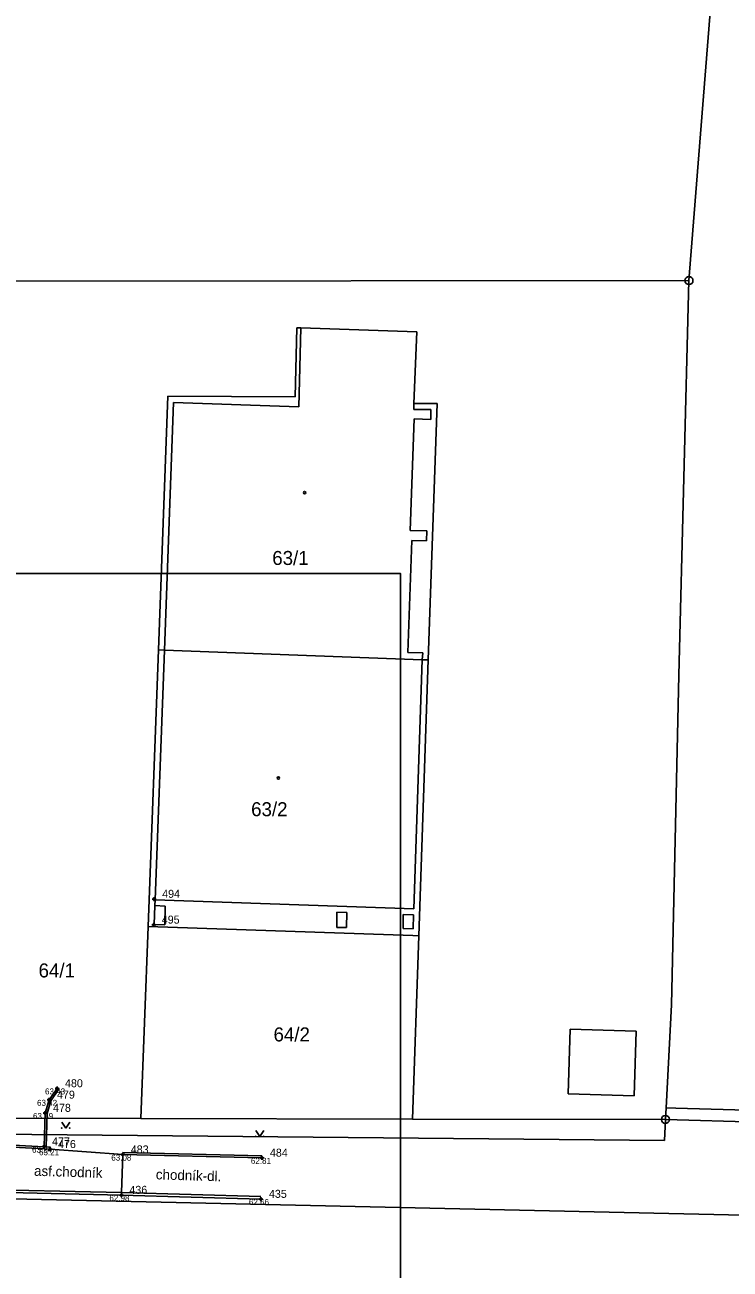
# Model space of a CAD drawing. Extents: x -454285 to -453563, y -1108687 to -1108249.
# Drawn here: x -453808.9 to -453773.6, y -1108476.5 to -1108414.3 of the extents above; entities that cross this region are included whole.
import ezdxf

# ---------------------------------------------------------------- set-up
doc = ezdxf.new("R2010")
doc.units = 0
for name, color, linetype in [('1', 7, 'Continuous'), ('14', 7, 'Continuous'), ('15', 7, 'Continuous'), ('2', 7, 'Continuous'), ('25', 7, 'Continuous'), ('28', 7, 'Continuous'), ('BODY_T1_2018', 7, 'Continuous'), ('CISLA_T1_2018', 7, 'Continuous'), ('obrubník', 7, 'Continuous'), ('rozhraní', 7, 'Continuous'), ('rámy', 7, 'Continuous'), ('T', 7, 'Continuous'), ('VYSKY_T1_2018', 7, 'Continuous'), ('zeleň', 7, 'Continuous')]:
    doc.layers.add(name, color=color, linetype=linetype)

# ---------------------------------------------------------------- blocks, each defined once
blk = doc.blocks.new('Z402')
for start, end in [(0, 180), (180, 0)]:
    blk.add_arc((0, 0), 0.15, start, end)
blk = doc.blocks.new('Z105')
for radius in [0.5, 0.01]:
    blk.add_circle((0, 0), radius)
blk = doc.blocks.new('PARK')
for p, q in [((0, 0), (-1, 1.5)), ((1, 1.5), (0, 0))]:
    blk.add_line(p, q)
for centre, start, end in [((-1, 0), 0, 180), ((1, 0), 0, 180), ((1, 0), 180, 0), ((-1, 0), 180, 0)]:
    blk.add_arc(centre, 0.05, start, end)
blk = doc.blocks.new('POINT_DISPLAY')
for p, q in [((-0.1, 0), (0.1, 0)), ((0, -0.1), (0, 0.1))]:
    blk.add_line(p, q)
blk.add_circle((0, 0), 0.05)
blk = doc.blocks.new('t1_2018')
at = {"layer": 'BODY_T1_2018'}
for p in [(-453802.46, -1108457.98), (-453802.48, -1108459.27), (-453807.32, -1108467.45), (-453807.72, -1108468.02), (-453807.92, -1108468.68), (-453807.97, -1108470.36), (-453807.67, -1108470.49), (-453804.03, -1108470.76), (-453797.07, -1108470.92), (-453804.1, -1108472.78), (-453797.12, -1108472.98)]:
    blk.add_blockref('POINT_DISPLAY', p, dxfattribs=at)
at = {"layer": 'CISLA_T1_2018'}
for s, p in [('494', (-453802.06, -1108457.92)), ('495', (-453802.08, -1108459.21)), ('480', (-453806.92, -1108467.39)), ('479', (-453807.32, -1108467.96)), ('478', (-453807.52, -1108468.62)), ('477', (-453807.57, -1108470.3)), ('476', (-453807.27, -1108470.43)), ('483', (-453803.63, -1108470.7)), ('484', (-453796.67, -1108470.86)), ('436', (-453803.7, -1108472.72)), ('435', (-453796.72, -1108472.92))]:
    blk.add_text(s, height=0.4, dxfattribs=at).set_placement(p)
at = {"layer": 'VYSKY_T1_2018'}
for s, p in [('63.43', (-453807.92, -1108467.75)), ('63.42', (-453808.32, -1108468.32)), ('63.39', (-453808.52, -1108468.98)), ('63.24', (-453808.57, -1108470.66)), ('63.21', (-453808.22, -1108470.79)), ('63.08', (-453804.605, -1108471.06)), ('62.81', (-453797.62, -1108471.22)), ('62.98', (-453804.7, -1108473.08)), ('62.66', (-453797.72, -1108473.28))]:
    blk.add_text(s, height=0.3, dxfattribs=at).set_placement(p)

msp = doc.modelspace()

# ---------------------------------------------------------------- linework, layer by layer
at = {"layer": '1'}
for p, q in [((-453774.627, -1108413.451), (-453775.707, -1108427.061)), ((-453809.507, -1108427.091), (-453775.707, -1108427.061)), ((-453775.707, -1108427.061), (-453776.207, -1108446.791)), ((-453795.317, -1108429.421), (-453795.407, -1108432.871)), ((-453795.317, -1108429.421), (-453795.117, -1108429.431)), ((-453795.117, -1108429.431), (-453789.317, -1108429.621)), ((-453789.317, -1108429.621), (-453789.467, -1108433.201)), ((-453801.777, -1108432.841), (-453802.247, -1108445.521)), ((-453795.407, -1108432.871), (-453801.777, -1108432.841)), ((-453789.467, -1108433.201), (-453788.307, -1108433.211)), ((-453788.307, -1108433.211), (-453788.747, -1108446.031)), ((-453802.247, -1108445.521), (-453802.767, -1108459.361)), ((-453802.247, -1108445.521), (-453801.947, -1108445.541)), ((-453801.947, -1108445.541), (-453789.047, -1108446.021)), ((-453789.217, -1108459.821), (-453788.747, -1108446.031)), ((-453788.747, -1108446.031), (-453789.047, -1108446.021)), ((-453776.207, -1108446.791), (-453776.577, -1108463.271)), ((-453802.767, -1108459.361), (-453803.127, -1108468.961)), ((-453802.767, -1108459.361), (-453789.517, -1108459.811)), ((-453789.217, -1108459.821), (-453789.537, -1108468.981)), ((-453789.517, -1108459.811), (-453789.217, -1108459.821)), ((-453776.577, -1108463.271), (-453776.857, -1108468.421)), ((-453897.257, -1108468.871), (-453776.927, -1108470.061)), ((-453776.857, -1108468.421), (-453776.887, -1108469.001)), ((-453803.127, -1108468.961), (-453811.757, -1108468.941)), ((-453803.127, -1108468.961), (-453789.537, -1108468.981)), ((-453789.537, -1108468.981), (-453776.887, -1108469.001)), ((-453776.887, -1108469.001), (-453776.927, -1108470.061)), ((-453767.457, -1108469.291), (-453776.887, -1108469.001))]:
    msp.add_line(p, q, dxfattribs=at)
at = {"layer": '2'}
for p, q in [((-453795.217, -1108433.371), (-453795.117, -1108429.431)), ((-453801.487, -1108433.151), (-453801.947, -1108445.541)), ((-453801.487, -1108433.151), (-453795.217, -1108433.371)), ((-453789.477, -1108433.501), (-453789.467, -1108433.201)), ((-453789.647, -1108439.551), (-453789.457, -1108433.981)), ((-453788.617, -1108433.511), (-453789.477, -1108433.501)), ((-453789.457, -1108433.981), (-453788.627, -1108434.011)), ((-453788.627, -1108434.011), (-453788.617, -1108433.511)), ((-453788.827, -1108439.581), (-453789.647, -1108439.551)), ((-453788.837, -1108440.081), (-453788.827, -1108439.581)), ((-453789.777, -1108445.651), (-453789.577, -1108440.051)), ((-453789.577, -1108440.051), (-453788.837, -1108440.081)), ((-453801.947, -1108445.541), (-453802.417, -1108458.021)), ((-453789.027, -1108445.671), (-453789.777, -1108445.651)), ((-453789.047, -1108446.021), (-453789.027, -1108445.671)), ((-453789.477, -1108458.471), (-453789.047, -1108446.021)), ((-453802.417, -1108458.021), (-453802.427, -1108458.311)), ((-453789.477, -1108458.471), (-453802.417, -1108458.021)), ((-453802.457, -1108459.261), (-453802.427, -1108458.311)), ((-453802.427, -1108458.311), (-453801.917, -1108458.331)), ((-453801.917, -1108458.331), (-453801.927, -1108459.271)), ((-453793.327, -1108459.411), (-453793.317, -1108458.631)), ((-453793.317, -1108458.631), (-453792.827, -1108458.651)), ((-453792.827, -1108458.651), (-453792.837, -1108459.411)), ((-453790.007, -1108459.461), (-453789.997, -1108458.751)), ((-453789.997, -1108458.751), (-453789.487, -1108458.771)), ((-453789.487, -1108458.771), (-453789.507, -1108459.471)), ((-453801.927, -1108459.271), (-453802.457, -1108459.261)), ((-453792.837, -1108459.411), (-453793.327, -1108459.411)), ((-453789.507, -1108459.471), (-453790.007, -1108459.461)), ((-453781.747, -1108467.721), (-453781.647, -1108464.481)), ((-453781.647, -1108464.481), (-453778.347, -1108464.581)), ((-453778.347, -1108464.581), (-453778.447, -1108467.821)), ((-453778.447, -1108467.821), (-453781.747, -1108467.721)), ((-453776.857, -1108468.421), (-453776.367, -1108468.431)), ((-453767.457, -1108468.701), (-453776.367, -1108468.431)), ((-453670.227, -1108476.061), (-453858.457, -1108471.891))]:
    msp.add_line(p, q, dxfattribs=at)
at = {"layer": 'obrubník'}
for points in [[(-453807.238, -1108467.507), (-453807.629, -1108468.064), (-453807.82, -1108468.696), (-453807.87, -1108470.363), (-453807.97, -1108470.36), (-453807.92, -1108468.68), (-453807.72, -1108468.02), (-453807.32, -1108467.45)], [(-453797.068, -1108470.82), (-453804.028, -1108470.66)], [(-453797.07, -1108470.92), (-453804.03, -1108470.76)], [(-453797.117, -1108472.86), (-453804.097, -1108472.66), (-453811.837, -1108472.48), (-453823.197, -1108472.18), (-453831.237, -1108471.99), (-453834.586, -1108471.9), (-453836.066, -1108471.84), (-453836.07, -1108471.96), (-453834.59, -1108472.02), (-453831.24, -1108472.11), (-453823.2, -1108472.3), (-453811.84, -1108472.6), (-453804.1, -1108472.78), (-453797.12, -1108472.98)]]:
    msp.add_lwpolyline(points, dxfattribs=at)
msp.add_lwpolyline([(-453807.665, -1108470.39), (-453811.665, -1108470.17), (-453811.67, -1108470.27), (-453807.67, -1108470.49)], close=True, dxfattribs=at)
at = {"layer": 'rozhraní'}
for points in [[(-453807.67, -1108470.49), (-453804.03, -1108470.76)], [(-453804.03, -1108470.76), (-453804.097, -1108472.66)]]:
    msp.add_lwpolyline(points, dxfattribs=at)
at = {"layer": 'rámy'}
msp.add_lwpolyline([(-453889.309, -1108441.707), (-453790.141, -1108441.707), (-453790.141, -1108501.759), (-453889.309, -1108501.759)], close=True, dxfattribs=at)

# ---------------------------------------------------------------- block references
msp.add_blockref('t1_2018', (0, 0))
at = {"layer": '25', "xscale": 0.4, "yscale": 0.4000000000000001}
for p in [(-453794.937, -1108437.661), (-453796.246, -1108451.931)]:
    msp.add_blockref('Z402', p, dxfattribs=at)
at = {"layer": '28', "xscale": 0.4, "yscale": 0.4000000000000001}
for p in [(-453775.707, -1108427.061), (-453776.887, -1108469.001)]:
    msp.add_blockref('Z105', p, dxfattribs=at)
at = {"layer": 'zeleň', "xscale": 0.2, "yscale": 0.20000000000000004}
for p in [(-453806.884, -1108469.434), (-453797.181, -1108469.846)]:
    msp.add_blockref('PARK', p, dxfattribs=at)

# ---------------------------------------------------------------- texts
at = {"layer": '14'}
for s, p in [('64/1', (-453808.243, -1108461.901)), ('64/2', (-453796.49, -1108465.101))]:
    msp.add_text(s, height=0.7, dxfattribs=at).set_placement(p)
at = {"layer": '15'}
for s, p in [('63/1', (-453796.553, -1108441.281)), ('63/2', (-453797.61, -1108453.841))]:
    msp.add_text(s, height=0.7, dxfattribs=at).set_placement(p)
at = {"layer": 'T'}
for s, p in [('asf.chodník', (-453808.475, -1108471.814)), ('chodník-dl.', (-453802.382, -1108471.993))]:
    msp.add_text(s, height=0.5, rotation=358.20729, dxfattribs=at).set_placement(p)

doc.saveas('drawing.dxf')
